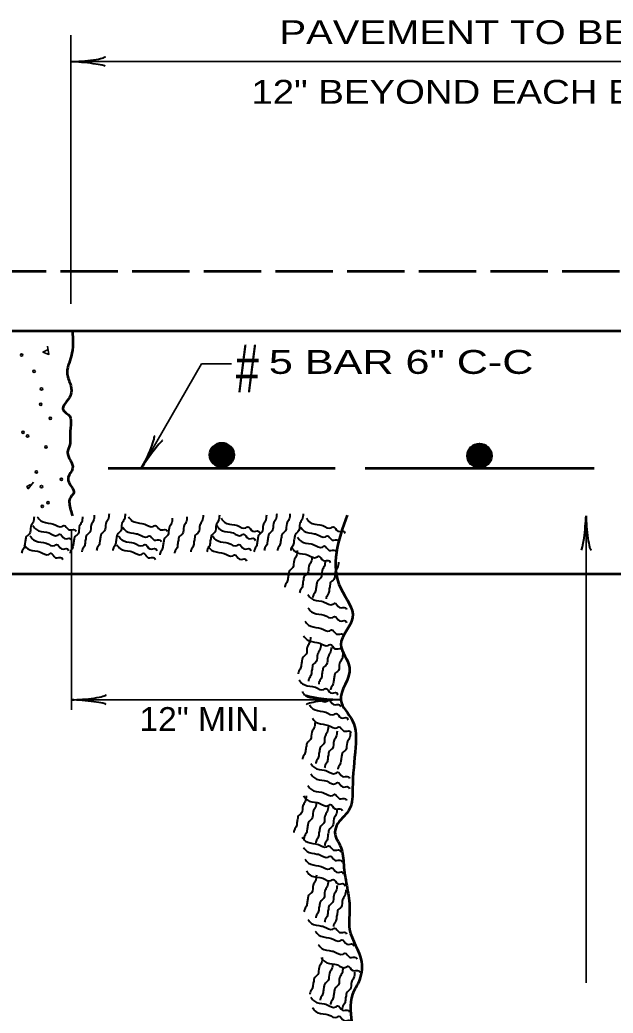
# Model space of a CAD drawing. Extents: x -488 to 193, y 19 to 459.
# Drawn here: x -240.1 to -190.5, y 277.1 to 360.3 of the extents above; entities that cross this region are included whole.
import ezdxf
from ezdxf.enums import TextEntityAlignment as Align

# ---------------------------------------------------------------- set-up
doc = ezdxf.new("R2010")
doc.units = 0
doc.header["$LTSCALE"] = 0.8
doc.linetypes.add('LONG_DASHED', pattern=[7.5, 6, -1.5])
doc.layers.add('1', color=7, linetype='Continuous', lineweight=40)

msp = doc.modelspace()

# ---------------------------------------------------------------- linework, layer by layer
at = {"layer": '1', "lineweight": 35}
for p, q in [((-235.8628, 336.5494), (-235.8628, 359.0494)), ((-235.8628, 356.8337), (-146.8628, 356.8337)), ((-192.7425, 279.6447), (-192.7425, 318.7816)), ((-235.8044, 317.5241), (-235.8044, 302.5241)), ((-235.8044, 303.3655), (-213.2937, 303.3655))]:
    msp.add_line(p, q, dxfattribs=at)
at = {"layer": '1', "linetype": 'LONG_DASHED', "lineweight": 53}
msp.add_line((-272.7425, 339.2816), (-112.7425, 339.2816), dxfattribs=at)
at = {"layer": '1', "lineweight": 53}
for p, q in [((-272.7425, 334.2816), (-112.7425, 334.2816)), ((-232.7425, 322.7816), (-213.7424, 322.7816)), ((-211.2339, 322.7816), (-192.0741, 322.7816)), ((-271.5283, 313.9212), (-111.5283, 313.9212))]:
    msp.add_line(p, q, dxfattribs=at)
at = {"layer": '1', "lineweight": 35}
for points in [[(-237.8351, 332.6768), (-238.2044, 332.4922), (-237.712, 332.3075), (-237.8351, 332.9847)], [(-229.9616, 322.7816), (-224.9216, 331.5111), (-222.4216, 331.5111)], [(-239.2509, 321.4117), (-239.5588, 321.227), (-239.4356, 321.0422), (-239.0047, 321.5963)]]:
    msp.add_lwpolyline(points, dxfattribs=at)
for centre in [(-239.9897, 332.2459), (-238.9432, 330.8916), (-238.3276, 329.4142), (-238.3891, 328.1215), (-237.5888, 326.9518), (-239.8665, 325.7822), (-239.4972, 325.4745), (-237.9582, 324.5511), (-238.7585, 322.4581), (-238.3276, 321.2269), (-236.6655, 321.8425), (-238.266, 319.5648), (-237.7735, 319.8727)]:
    msp.add_circle(centre, 0.1, dxfattribs=at)
at = {"layer": '1', "lineweight": 53}
for centre, radius in [((-223.2356, 323.8787), 1), ((-223.2397, 323.8601), 0.9157), ((-223.2417, 323.9178), 0.86), ((-223.2397, 323.8931), 0.8006), ((-223.2294, 323.8663), 0.7367), ((-201.6699, 323.8127), 1), ((-201.674, 323.7941), 0.9157), ((-201.6761, 323.8518), 0.86), ((-201.674, 323.8271), 0.8006), ((-223.2191, 323.856), 0.6773), ((-223.2088, 323.8581), 0.6185), ((-223.2026, 323.8663), 0.5611), ((-223.1964, 323.889), 0.5056), ((-223.1965, 323.891), 0.4402), ((-223.1862, 323.8951), 0.3756), ((-223.1882, 323.8951), 0.316), ((-223.1923, 323.9116), 0.2543), ((-223.1902, 323.9055), 0.1899), ((-223.1882, 323.9116), 0.1383), ((-223.1799, 323.9034), 0.0846), ((-223.18, 323.9055), 0.0356), ((-201.6637, 323.8003), 0.7367), ((-201.6535, 323.79), 0.6773), ((-201.6431, 323.7921), 0.6185), ((-201.637, 323.8003), 0.5611), ((-201.6308, 323.823), 0.5056), ((-201.6308, 323.825), 0.4402), ((-201.6205, 323.8291), 0.3756), ((-201.6225, 323.8291), 0.316), ((-201.6267, 323.8456), 0.2543), ((-201.6246, 323.8395), 0.1899), ((-201.6225, 323.8456), 0.1383), ((-201.6142, 323.8374), 0.0846), ((-201.6143, 323.8395), 0.0356)]:
    msp.add_circle(centre, radius, dxfattribs=at)
at = {"layer": '1'}
for centre, major_axis, ratio, start_param, end_param in [((-234.7716, 357.11), (-1.7857, -0.1562), 0.122415, 0.8963533, 3.1415927), ((-234.7422, 356.6221), (1.7565, -0.1757), 0.07063, 6.2823074, 8.5597026), ((-229.6553, 323.8647), (-0.7576, -1.6245), 0.122415, 0.8963533, 3.1415927), ((-229.2181, 323.6462), (1.0303, 1.4333), 0.07063, 6.2823074, 8.5597026), ((-192.9541, 317.6611), (-0.1757, -1.7565), 0.07063, 6.2823074, 8.5597026), ((-192.9541, 317.6611), (-0.1757, -1.7565), 0.07063, 6.2823074, 8.5597026), ((-192.4662, 317.6904), (-0.1562, 1.7857), 0.122415, 0.8963533, 3.1415927), ((-192.4662, 317.6904), (-0.1562, 1.7857), 0.122415, 0.8963533, 3.1415927), ((-234.7132, 303.6418), (-1.7857, -0.1562), 0.122415, 0.8963533, 3.1415927), ((-234.7132, 303.6418), (-1.7857, -0.1562), 0.122415, 0.8963533, 3.1415927), ((-234.6839, 303.1539), (1.7565, -0.1757), 0.07063, 6.2823074, 8.5597026), ((-234.6839, 303.1539), (1.7565, -0.1757), 0.07063, 6.2823074, 8.5597026), ((-214.3849, 303.0892), (1.7857, 0.1562), 0.122415, 0.8963533, 3.1415927), ((-214.4142, 303.5771), (1.7565, -0.1757), 0.07063, 3.1407148, 5.41811)]:
    msp.add_ellipse(centre, major_axis=major_axis, ratio=ratio, start_param=start_param, end_param=end_param, dxfattribs=at)
at = {"layer": '1', "lineweight": 53}
for points in [[(-235.7428, 334.2767), (-235.8421, 332.1335), (-236.1807, 330.6561), (-235.8728, 329.6712), (-235.9036, 328.8709), (-236.5192, 327.6397), (-235.9652, 327.1165), (-235.8728, 326.4086), (-235.9344, 325.3313), (-235.9652, 324.7158), (-236.1498, 324.1002), (-235.7189, 322.7459), (-236.0883, 321.9764), (-235.996, 321.484), (-235.6266, 320.7145), (-235.9652, 320.222), (-235.996, 319.8219), (-235.7425, 318.7816)], [(-212.7425, 318.8428), (-213.2734, 312.6869), (-212.2884, 310.2246), (-213.2734, 308.0085), (-212.5347, 306.0386), (-213.2734, 303.3301), (-212.2884, 301.6064), (-212.0422, 299.3903), (-212.2884, 295.943), (-212.5347, 294.2194), (-213.5196, 292.9882), (-213.7658, 292.2495), (-213.2734, 291.0183), (-213.0272, 289.5409), (-212.7809, 287.8173), (-212.5347, 286.0937), (-212.5347, 284.1237), (-211.5497, 281.4152), (-211.796, 279.6916), (-212.2884, 278.7066), (-212.2884, 275.9981), (-212.0422, 272.797), (-212.2884, 271.5658), (-212.2884, 268.8572), (-212.7809, 265.41), (-212.7809, 262.9477), (-213.7658, 259.7466), (-213.0272, 258.0229), (-213.2734, 255.8068), (-213.5196, 253.0982), (-213.2734, 251.3746), (-213.0272, 248.4198), (-212.7809, 246.6962), (-213.0272, 244.7263), (-213.0272, 241.5252), (-212.2884, 240.7866), (-212.7809, 236.8468), (-212.7809, 234.6307), (-212.5347, 233.1532), (-213.0272, 230.1985), (-212.5347, 228.9673), (-213.0272, 226.7512), (-212.5347, 225.7662), (-210.5648, 223.7964), (-208.8412, 224.2888), (-207.1175, 225.52), (-205.6401, 224.2888), (-204.1627, 224.0426), (-200.9617, 224.0426), (-197.7606, 225.2738), (-196.7757, 224.5351), (-192.5897, 224.5351), (-188.8962, 225.0276), (-186.9263, 224.5351), (-182.7403, 225.0276), (-181.2629, 224.7813), (-176.8307, 225.0276), (-176.3382, 224.2888), (-173.3834, 224.7813), (-171.1673, 227.7362), (-171.4136, 229.4597), (-171.6598, 230.4447), (-173.1372, 235.1232), (-171.1673, 238.3242), (-172.3985, 241.0327), (-172.3985, 242.0177), (-171.4136, 243.7413), (-171.906, 246.4499), (-171.1673, 247.6811), (-170.1824, 250.1434), (-171.6598, 254.3294), (-171.6598, 255.8068), (-171.4136, 257.5305), (-172.1522, 259.7466), (-171.906, 261.224), (-172.1522, 263.9326), (-173.1372, 267.3798), (-171.6598, 270.0884), (-171.4136, 272.3045), (-171.1673, 275.9981), (-171.4136, 277.9679), (-172.1522, 279.6916), (-172.1522, 281.169), (-171.906, 284.1237), (-172.891, 287.0786), (-173.1372, 289.7872), (-171.4136, 292.4957), (-172.1522, 294.4656), (-172.3985, 295.6968), (-171.1673, 298.6516), (-172.1522, 300.8677), (-172.1522, 305.0537), (-171.906, 306.5311), (-171.6598, 308.0085), (-172.6447, 310.7171), (-172.891, 312.1945), (-172.7425, 318.8428)]]:
    msp.add_spline(points, degree=3, dxfattribs=at)
at = {"layer": '1'}
for points in [[(-233.9053, 318.8288), (-233.9908, 318.3439), (-234.1762, 318.0016), (-234.2831, 317.3952), (-234.5898, 317.0743), (-234.6111, 316.9532), (-234.6753, 316.5893), (-234.7393, 316.2256), (-234.9248, 315.8833), (-234.9462, 315.762)], [(-232.6742, 318.9519), (-232.7597, 318.467), (-232.945, 318.1247), (-233.0519, 317.5183), (-233.3587, 317.1974), (-233.3799, 317.0763), (-233.4441, 316.7124), (-233.5082, 316.3487), (-233.6937, 316.0064), (-233.7151, 315.8851)], [(-231.3199, 318.9519), (-231.4054, 318.467), (-231.5907, 318.1247), (-231.6977, 317.5183), (-232.0044, 317.1974), (-232.0257, 317.0763), (-232.0898, 316.7124), (-232.1539, 316.3487), (-232.3394, 316.0064), (-232.3608, 315.8851)], [(-224.7947, 318.8288), (-224.8802, 318.3439), (-225.0655, 318.0016), (-225.1724, 317.3952), (-225.4792, 317.0743), (-225.5004, 316.9532), (-225.5646, 316.5893), (-225.6287, 316.2256), (-225.8142, 315.8833), (-225.8356, 315.762)], [(-223.4404, 318.8288), (-223.5259, 318.3439), (-223.7112, 318.0016), (-223.8182, 317.3952), (-224.1249, 317.0743), (-224.1462, 316.9532), (-224.2103, 316.5893), (-224.2744, 316.2256), (-224.4599, 315.8833), (-224.4813, 315.762)], [(-219.5007, 318.8288), (-219.5862, 318.3439), (-219.7715, 318.0016), (-219.8784, 317.3952), (-220.1852, 317.0743), (-220.2064, 316.9532), (-220.2706, 316.5893), (-220.3347, 316.2256), (-220.5202, 315.8833), (-220.5416, 315.762)], [(-218.6388, 318.9519), (-218.7243, 318.467), (-218.9097, 318.1247), (-219.0166, 317.5183), (-219.3233, 317.1974), (-219.3446, 317.0763), (-219.4087, 316.7124), (-219.4728, 316.3487), (-219.6583, 316.0064), (-219.6797, 315.8851)], [(-217.5307, 318.9519), (-217.6162, 318.467), (-217.8016, 318.1247), (-217.9085, 317.5183), (-218.2152, 317.1974), (-218.2365, 317.0763), (-218.3007, 316.7124), (-218.3647, 316.3487), (-218.5503, 316.0064), (-218.5717, 315.8851)], [(-216.4227, 318.9519), (-216.5083, 318.467), (-216.6936, 318.1247), (-216.8005, 317.5183), (-217.1072, 317.1974), (-217.1285, 317.0763), (-217.1927, 316.7124), (-217.2567, 316.3487), (-217.4423, 316.0064), (-217.4637, 315.8851)], [(-238.9532, 318.7057), (-239.0387, 318.2208), (-239.224, 317.8784), (-239.3309, 317.2721), (-239.6377, 316.9512), (-239.6589, 316.83), (-239.7231, 316.4662), (-239.7872, 316.1024), (-239.9727, 315.7602), (-239.9941, 315.6388)], [(-239.0476, 317.9612), (-238.7547, 317.6276), (-237.9222, 317.4046), (-237.6843, 317.3409), (-236.9708, 317.1497), (-236.82, 317.2367), (-236.4079, 316.8715), (-235.9005, 316.8628), (-235.8134, 316.7122)], [(-238.6782, 318.6998), (-238.3853, 318.3662), (-237.5528, 318.1432), (-237.315, 318.0796), (-236.6015, 317.8883), (-236.4507, 317.9754), (-236.0386, 317.6102), (-235.5312, 317.6015), (-235.4441, 317.4508)], [(-234.8903, 318.7057), (-234.9758, 318.2208), (-235.1612, 317.8784), (-235.2681, 317.2721), (-235.5748, 316.9512), (-235.5961, 316.83), (-235.6602, 316.4662), (-235.7243, 316.1024), (-235.9098, 315.7602), (-235.9313, 315.6388)], [(-231.045, 318.6997), (-230.7521, 318.3662), (-229.9196, 318.1432), (-229.6817, 318.0795), (-228.9682, 317.8882), (-228.8174, 317.9753), (-228.4053, 317.6101), (-227.8979, 317.6014), (-227.8108, 317.4507)], [(-227.3802, 318.5826), (-227.4657, 318.0977), (-227.651, 317.7553), (-227.7579, 317.149), (-228.0647, 316.8281), (-228.0859, 316.7069), (-228.1501, 316.3431), (-228.2142, 315.9793), (-228.3997, 315.6371), (-228.4211, 315.5157)], [(-226.149, 318.7057), (-226.2345, 318.2208), (-226.4198, 317.8784), (-226.5267, 317.2721), (-226.8335, 316.9512), (-226.8547, 316.83), (-226.9189, 316.4662), (-226.983, 316.1024), (-227.1685, 315.7602), (-227.1899, 315.6388)], [(-223.6579, 317.9611), (-223.365, 317.6275), (-222.5325, 317.4045), (-222.2947, 317.3408), (-221.5812, 317.1496), (-221.4303, 317.2367), (-221.0182, 316.8714), (-220.5108, 316.8628), (-220.4237, 316.7121)], [(-223.2886, 318.5767), (-222.9957, 318.2431), (-222.1632, 318.0201), (-221.9253, 317.9564), (-221.2118, 317.7652), (-221.061, 317.8522), (-220.6489, 317.487), (-220.1415, 317.4783), (-220.0544, 317.3277)], [(-216.1478, 318.5767), (-215.8549, 318.2431), (-215.0224, 318.0201), (-214.7846, 317.9564), (-214.0711, 317.7652), (-213.9202, 317.8522), (-213.5082, 317.487), (-213.0007, 317.4783), (-212.9137, 317.3277)], [(-239.2938, 317.0993), (-239.0009, 316.7657), (-238.1684, 316.5428), (-237.9306, 316.4791), (-237.2171, 316.2878), (-237.0662, 316.3749), (-236.6542, 316.0097), (-236.1467, 316.001), (-236.0597, 315.8503)], [(-231.9068, 317.0992), (-231.6139, 316.7657), (-230.7814, 316.5427), (-230.5436, 316.479), (-229.8301, 316.2878), (-229.6792, 316.3748), (-229.2672, 316.0096), (-228.7597, 316.0009), (-228.6727, 315.8503)], [(-231.5374, 317.8379), (-231.2445, 317.5043), (-230.412, 317.2813), (-230.1742, 317.2177), (-229.4607, 317.0264), (-229.3098, 317.1135), (-228.8978, 316.7482), (-228.3903, 316.7396), (-228.3032, 316.5889)], [(-224.0272, 317.0992), (-223.7343, 316.7657), (-222.9018, 316.5427), (-222.664, 316.479), (-221.9505, 316.2878), (-221.7997, 316.3748), (-221.3876, 316.0096), (-220.8802, 316.0009), (-220.7931, 315.8503)], [(-216.6402, 317.838), (-216.3473, 317.5044), (-215.5148, 317.2814), (-215.277, 317.2177), (-214.5635, 317.0265), (-214.4127, 317.1136), (-214.0006, 316.7483), (-213.4932, 316.7397), (-213.4061, 316.589)], [(-239.7862, 316.3606), (-239.4933, 316.027), (-238.6608, 315.804), (-238.423, 315.7403), (-237.7095, 315.5491), (-237.5587, 315.6362), (-237.1466, 315.2709), (-236.6392, 315.2622), (-236.5521, 315.1116)], [(-232.0299, 316.3605), (-231.737, 316.0269), (-230.9045, 315.8039), (-230.6667, 315.7403), (-229.9532, 315.549), (-229.8023, 315.6361), (-229.3902, 315.2708), (-228.8828, 315.2622), (-228.7957, 315.1115)], [(-224.3966, 316.2374), (-224.1037, 315.9038), (-223.2712, 315.6808), (-223.0333, 315.6172), (-222.3198, 315.4259), (-222.169, 315.513), (-221.7569, 315.1477), (-221.2495, 315.1391), (-221.1624, 314.9884)], [(-216.8865, 316.9762), (-216.5936, 316.6426), (-215.7611, 316.4196), (-215.5232, 316.3559), (-214.8097, 316.1647), (-214.6589, 316.2518), (-214.2468, 315.8865), (-213.7394, 315.8778), (-213.6523, 315.7272)], [(-216.9152, 315.874), (-217.0007, 315.3891), (-217.186, 315.0467), (-217.2929, 314.4404), (-217.5997, 314.1195), (-217.6209, 313.9983), (-217.6851, 313.6345), (-217.7492, 313.2707), (-217.9347, 312.9285), (-217.9561, 312.8072)], [(-217.379, 316.1143), (-217.0861, 315.7808), (-216.2536, 315.5577), (-216.0157, 315.4941), (-215.3022, 315.3028), (-215.1514, 315.3899), (-214.7393, 315.0247), (-214.2319, 315.016), (-214.1448, 314.8653)], [(-215.684, 315.3815), (-215.7695, 314.8966), (-215.9548, 314.5542), (-216.0617, 313.9479), (-216.3685, 313.627), (-216.3897, 313.5058), (-216.4539, 313.142), (-216.518, 312.7783), (-216.7035, 312.436), (-216.7249, 312.3147)], [(-214.576, 315.0122), (-214.6615, 314.5272), (-214.8468, 314.1849), (-214.9537, 313.5786), (-215.2605, 313.2577), (-215.2817, 313.1365), (-215.3459, 312.7727), (-215.41, 312.4089), (-215.5955, 312.0667), (-215.6169, 311.9453)], [(-213.4679, 314.889), (-213.5534, 314.4041), (-213.7387, 314.0618), (-213.8457, 313.4554), (-214.1524, 313.1345), (-214.1737, 313.0133), (-214.2378, 312.6495), (-214.3019, 312.2858), (-214.4874, 311.9435), (-214.5088, 311.8222)], [(-216.0247, 312.1746), (-215.7318, 311.841), (-214.8992, 311.618), (-214.6614, 311.5543), (-213.9479, 311.3631), (-213.7971, 311.4502), (-213.385, 311.0849), (-212.8776, 311.0763), (-212.7905, 310.9256)], [(-216.0247, 311.0666), (-215.7318, 310.733), (-214.8992, 310.51), (-214.6614, 310.4463), (-213.9479, 310.2551), (-213.7971, 310.3422), (-213.385, 309.9769), (-212.8776, 309.9683), (-212.7905, 309.8176)], [(-216.2709, 309.9585), (-215.978, 309.6249), (-215.1455, 309.4019), (-214.9077, 309.3383), (-214.1942, 309.147), (-214.0433, 309.2341), (-213.6312, 308.8688), (-213.1238, 308.8602), (-213.0367, 308.7095)], [(-215.8072, 308.61), (-215.8927, 308.1251), (-216.078, 307.7827), (-216.1849, 307.1764), (-216.4917, 306.8555), (-216.5129, 306.7343), (-216.5771, 306.3705), (-216.6412, 306.0068), (-216.8267, 305.6645), (-216.8481, 305.5432)], [(-216.394, 308.7273), (-216.1011, 308.3938), (-215.2686, 308.1707), (-215.0307, 308.1071), (-214.3173, 307.9158), (-214.1664, 308.0029), (-213.7543, 307.6377), (-213.2469, 307.629), (-213.1598, 307.4783)], [(-214.9453, 307.9945), (-215.0308, 307.5096), (-215.2162, 307.1672), (-215.3231, 306.5609), (-215.6298, 306.24), (-215.6511, 306.1188), (-215.7152, 305.755), (-215.7793, 305.3913), (-215.9648, 305.049), (-215.9862, 304.9277)], [(-214.0835, 307.7482), (-214.169, 307.2633), (-214.3543, 306.921), (-214.4613, 306.3147), (-214.768, 305.9937), (-214.7892, 305.8726), (-214.8534, 305.5087), (-214.9175, 305.145), (-215.103, 304.8028), (-215.1244, 304.6814)], [(-213.0986, 307.2558), (-213.1841, 306.7709), (-213.3694, 306.4286), (-213.4763, 305.8222), (-213.7831, 305.5013), (-213.8043, 305.3802), (-213.8685, 305.0163), (-213.9326, 304.6526), (-214.1181, 304.3103), (-214.1395, 304.189)], [(-216.7633, 305.0337), (-216.4704, 304.7002), (-215.6379, 304.4772), (-215.4001, 304.4135), (-214.6866, 304.2222), (-214.5357, 304.3093), (-214.1237, 303.9441), (-213.6162, 303.9354), (-213.5292, 303.7847)], [(-216.5171, 304.0488), (-216.2242, 303.7152), (-215.3917, 303.4923), (-215.1538, 303.4286), (-214.4403, 303.2373), (-214.2895, 303.3244), (-213.8774, 302.9592), (-213.37, 302.9505), (-213.2829, 302.7998)], [(-215.9015, 302.9407), (-215.6086, 302.6072), (-214.7761, 302.3842), (-214.5383, 302.3205), (-213.8247, 302.1293), (-213.6739, 302.2163), (-213.2618, 301.8511), (-212.7544, 301.8424), (-212.6673, 301.6918)], [(-215.4378, 301.4692), (-215.5233, 300.9843), (-215.7087, 300.642), (-215.8156, 300.0357), (-216.1223, 299.7147), (-216.1436, 299.5936), (-216.2078, 299.2297), (-216.2718, 298.866), (-216.4573, 298.5238), (-216.4787, 298.4024)], [(-215.6553, 301.8327), (-215.3624, 301.4992), (-214.5299, 301.2762), (-214.2921, 301.2125), (-213.5786, 301.0213), (-213.4278, 301.1083), (-213.0157, 300.7431), (-212.5083, 300.7344), (-212.4212, 300.5838)], [(-214.3297, 301.0999), (-214.4152, 300.615), (-214.6006, 300.2727), (-214.7075, 299.6663), (-215.0143, 299.3454), (-215.0355, 299.2242), (-215.0997, 298.8604), (-215.1637, 298.4967), (-215.3492, 298.1544), (-215.3707, 298.0331)], [(-213.591, 300.7306), (-213.6765, 300.2457), (-213.8618, 299.9033), (-213.9688, 299.297), (-214.2755, 298.9761), (-214.2968, 298.8549), (-214.3609, 298.4911), (-214.425, 298.1273), (-214.6105, 297.7851), (-214.6319, 297.6637)], [(-212.483, 300.6074), (-212.5685, 300.1225), (-212.7538, 299.7802), (-212.8607, 299.1738), (-213.1675, 298.8529), (-213.1887, 298.7317), (-213.2529, 298.3679), (-213.317, 298.0042), (-213.5025, 297.6619), (-213.5239, 297.5406)], [(-215.7784, 298.0161), (-215.4855, 297.6825), (-214.653, 297.4595), (-214.4152, 297.3958), (-213.7017, 297.2046), (-213.5508, 297.2917), (-213.1387, 296.9264), (-212.6313, 296.9178), (-212.5443, 296.7671)], [(-215.7784, 297.1542), (-215.4855, 296.8207), (-214.653, 296.5977), (-214.4152, 296.534), (-213.7017, 296.3427), (-213.5508, 296.4298), (-213.1387, 296.0646), (-212.6313, 296.0559), (-212.5443, 295.9052)], [(-216.0247, 296.1693), (-215.7318, 295.8357), (-214.8992, 295.6128), (-214.6614, 295.5491), (-213.9479, 295.3578), (-213.7971, 295.4449), (-213.385, 295.0797), (-212.8776, 295.071), (-212.7905, 294.9203)], [(-216.1765, 295.3135), (-216.262, 294.8286), (-216.4473, 294.4862), (-216.5542, 293.8799), (-216.861, 293.559), (-216.8822, 293.4378), (-216.9464, 293.074), (-217.0105, 292.7102), (-217.196, 292.368), (-217.2174, 292.2467)], [(-216.394, 295.3075), (-216.1011, 294.9739), (-215.2686, 294.7509), (-215.0307, 294.6873), (-214.3173, 294.496), (-214.1664, 294.5831), (-213.7543, 294.2178), (-213.2469, 294.2092), (-213.1598, 294.0585)], [(-215.3147, 294.821), (-215.4002, 294.3361), (-215.5855, 293.9937), (-215.6924, 293.3874), (-215.9992, 293.0665), (-216.0204, 292.9453), (-216.0846, 292.5815), (-216.1487, 292.2177), (-216.3342, 291.8755), (-216.3556, 291.7542)], [(-214.3297, 294.4517), (-214.4152, 293.9667), (-214.6006, 293.6244), (-214.7075, 293.0181), (-215.0143, 292.6972), (-215.0355, 292.576), (-215.0997, 292.2122), (-215.1637, 291.8484), (-215.3492, 291.5062), (-215.3707, 291.3848)], [(-213.591, 294.2054), (-213.6765, 293.7205), (-213.8618, 293.3782), (-213.9688, 292.7718), (-214.2755, 292.4509), (-214.2968, 292.3297), (-214.3609, 291.9659), (-214.425, 291.6022), (-214.6105, 291.2599), (-214.6319, 291.1386)], [(-216.5172, 291.8603), (-216.2242, 291.5267), (-215.3918, 291.3037), (-215.1539, 291.24), (-214.4404, 291.0487), (-214.2896, 291.1358), (-213.8775, 290.7706), (-213.3701, 290.7619), (-213.283, 290.6112)], [(-216.394, 290.9984), (-216.1011, 290.6648), (-215.2686, 290.4418), (-215.0307, 290.3782), (-214.3173, 290.1869), (-214.1664, 290.274), (-213.7543, 289.9087), (-213.2469, 289.9001), (-213.1598, 289.7494)], [(-216.2709, 290.0135), (-215.978, 289.6799), (-215.1455, 289.4569), (-214.9077, 289.3932), (-214.1942, 289.202), (-214.0433, 289.2891), (-213.6312, 288.9238), (-213.1238, 288.9152), (-213.0367, 288.7645)], [(-216.1478, 289.0286), (-215.8548, 288.695), (-215.0223, 288.472), (-214.7845, 288.4083), (-214.071, 288.2171), (-213.9202, 288.3042), (-213.5081, 287.9389), (-213.0007, 287.9303), (-212.9136, 287.7796)], [(-215.3147, 288.6651), (-215.4002, 288.1802), (-215.5855, 287.8378), (-215.6924, 287.2315), (-215.9992, 286.9106), (-216.0204, 286.7894), (-216.0846, 286.4256), (-216.1487, 286.0618), (-216.3342, 285.7196), (-216.3556, 285.5983)], [(-214.3297, 288.1726), (-214.4152, 287.6877), (-214.6006, 287.3453), (-214.7075, 286.739), (-215.0143, 286.4181), (-215.0355, 286.2969), (-215.0997, 285.9331), (-215.1637, 285.5693), (-215.3492, 285.2271), (-215.3707, 285.1058)], [(-213.591, 287.8032), (-213.6765, 287.3183), (-213.8618, 286.976), (-213.9688, 286.3697), (-214.2755, 286.0487), (-214.2968, 285.9276), (-214.3609, 285.5637), (-214.425, 285.2), (-214.6105, 284.8578), (-214.6319, 284.7364)], [(-212.8523, 287.4339), (-212.9378, 286.949), (-213.1232, 286.6067), (-213.2301, 286.0003), (-213.5368, 285.6794), (-213.5581, 285.5582), (-213.6222, 285.1944), (-213.6863, 284.8307), (-213.8718, 284.4884), (-213.8932, 284.3671)], [(-216.0247, 284.9657), (-215.7318, 284.6321), (-214.8992, 284.4091), (-214.6614, 284.3454), (-213.9479, 284.1542), (-213.7971, 284.2412), (-213.385, 283.876), (-212.8776, 283.8673), (-212.7905, 283.7167)], [(-215.4091, 283.9808), (-215.1162, 283.6472), (-214.2837, 283.4242), (-214.0458, 283.3605), (-213.3323, 283.1692), (-213.1815, 283.2563), (-212.7694, 282.8911), (-212.262, 282.8824), (-212.1749, 282.7317)], [(-215.1628, 282.8727), (-214.8699, 282.5391), (-214.0374, 282.3161), (-213.7996, 282.2524), (-213.0861, 282.0612), (-212.9352, 282.1483), (-212.5232, 281.783), (-212.0157, 281.7743), (-211.9287, 281.6237)], [(-214.8222, 281.7706), (-214.9077, 281.2857), (-215.093, 280.9433), (-215.1999, 280.337), (-215.5067, 280.0161), (-215.5279, 279.8949), (-215.5921, 279.5311), (-215.6562, 279.1673), (-215.8417, 278.8251), (-215.8631, 278.7038)], [(-214.9166, 281.7646), (-214.6237, 281.431), (-213.7912, 281.208), (-213.5533, 281.1443), (-212.8398, 280.9531), (-212.689, 281.0402), (-212.2769, 280.6749), (-211.7695, 280.6662), (-211.6824, 280.5156)], [(-213.9603, 281.2781), (-214.0458, 280.7932), (-214.2312, 280.4508), (-214.3381, 279.8445), (-214.6448, 279.5236), (-214.6661, 279.4024), (-214.7302, 279.0386), (-214.7943, 278.6748), (-214.9798, 278.3326), (-215.0012, 278.2113)], [(-213.0986, 280.9087), (-213.1841, 280.4238), (-213.3694, 280.0815), (-213.4763, 279.4752), (-213.7831, 279.1542), (-213.8043, 279.0331), (-213.8685, 278.6692), (-213.9326, 278.3055), (-214.1181, 277.9633), (-214.1395, 277.8419)], [(-212.1136, 280.5393), (-212.1991, 280.0544), (-212.3844, 279.7121), (-212.4913, 279.1058), (-212.7981, 278.7848), (-212.8193, 278.6637), (-212.8835, 278.2998), (-212.9476, 277.9361), (-213.1331, 277.5938), (-213.1545, 277.4725)], [(-215.7784, 278.4405), (-215.4855, 278.1069), (-214.653, 277.8839), (-214.4152, 277.8202), (-213.7017, 277.629), (-213.5508, 277.7161), (-213.1387, 277.3508), (-212.6313, 277.3422), (-212.5443, 277.1915)], [(-215.6553, 277.5787), (-215.3624, 277.2451), (-214.5299, 277.0221), (-214.2921, 276.9584), (-213.5786, 276.7672), (-213.4278, 276.8542), (-213.0157, 276.489), (-212.5083, 276.4803), (-212.4212, 276.3297)]]:
    msp.add_spline(points, degree=3, dxfattribs=at)

# ---------------------------------------------------------------- texts
for s, height, width, p in [('PAVEMENT TO BE CUT AT LEAST', 2, 1.25, (-191.4725, 358.3016)), ('12" BEYOND EACH EDGE OF TRENCH', 2, 1.2, (-191.4725, 353.3016)), ('#', 4, 0.65, (-221.1004, 329.1369)), ('12" MIN.', 2, 1.05, (-224.7117, 300.7485))]:
    msp.add_text(s, height=height, dxfattribs=dict(at, width=width)).set_placement(p, align=Align.CENTER)
at = {"layer": '1', "width": 1.35}
msp.add_text('5 BAR 6" C-C', height=2, dxfattribs=at).set_placement((-219.2968, 330.6704))

doc.saveas('drawing.dxf')
